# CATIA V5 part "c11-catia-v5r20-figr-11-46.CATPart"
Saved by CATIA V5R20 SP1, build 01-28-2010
Part number: Part2
Bounding box of the stored display mesh (mm): x 0 to 0, y -71.701 to 140, z -97.468 to 20
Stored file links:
  D:\v5_r20\psrt_files_downloaded\c11\c11-catia-v5r20-figr-11-46.CATPart
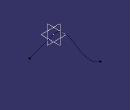
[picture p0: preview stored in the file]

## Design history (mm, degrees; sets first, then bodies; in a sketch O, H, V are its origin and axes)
Set1
  Extrapol1: ToExtrapol Sketch1.O, Support Sketch1, Length 121
Body1 (main body)
  Sketch1 on yz-plane, origin (0, 0, 0), H (0, 1, 0), V (0, 0, 1)
    spline S1 through (0, 0) (30, 20) (100, -10) (140, 0)
    point P1 (0, 0)
    coincidence: P1 O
